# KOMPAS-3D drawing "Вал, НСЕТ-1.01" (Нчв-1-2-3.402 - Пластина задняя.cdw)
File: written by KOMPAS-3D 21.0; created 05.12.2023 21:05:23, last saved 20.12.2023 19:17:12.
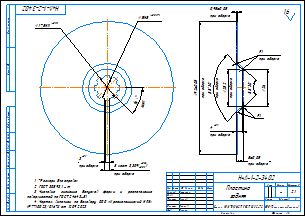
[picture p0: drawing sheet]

Sheet 1: A3, landscape

Document properties: Полное имя файла: D:\Точная технодинамика\04.12.2023\для отправки\центробежный насос нчв-1-2-3 (6) (готово)\Нчв-1-2-3.402 - Пластина задняя.cdw; Автор: zaycev_alexandr@mail.ru; Параметр неуказанной шероховатости: 1,6

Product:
- Part/product: Вал  | designation НСЕТ-1.01
    Материал: Сталь 10Х17Н13М2Т(ЭИ448) ГОСТ 5632-2014 (density 8000 kg/m3)
    Масса: 2.553371
    Форматы листов документа: A4
    source file: НСЕТ-1.01 - Вал.cdw

Title block, sheet 1: Наименование: Пластина / задняя; designation: Нчв-1-2-3 . 402; Материал: Сталь 10Х17Н13М2Т ГОСТ 5632-72; scale: 2:1; Количество листов документа: 1; organisation: ООО "Точная технодинамика"; Форматы листов документа: A3; stored path: E:\Точная технодинамика\Задания\ООО «Красноленинский НПЗ»\Чертежи\НСЕТ-1.01 - Вал.cdw; Разработал: Дущенко; Т. контр.: Серков; Н. контр.: Юсупов; Утвердил: Елагин

Views: Разрез 6, Вид 7
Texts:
  шаг
  при сборке
  Версия вида
  Тип вида
  Матрица вида
  Точка разреза
  ElectricLineNodes
  es-vk-info-doc
  es-ov-info-doc
  es-tx-info-doc
Dimensions and other numbers on the sheet: 17,5; 15; 0,95; 26; 1; 5; 4; 25,2; 88 30'; 92; 3; 8 мест; 3,3; 1,6; 2:1

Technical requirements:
  *Размеры для справок.
  ГОСТ 30893.1 - m.
  Числовые значения допусков формы и расположения
  поверхностей по ГОСТ 24643-81.
  Чертеж выполнен по договору ООО «Красноленинский НПЗ»
  №7710023/0167Д от 12.09.2023.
